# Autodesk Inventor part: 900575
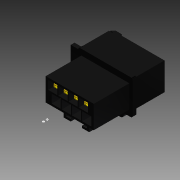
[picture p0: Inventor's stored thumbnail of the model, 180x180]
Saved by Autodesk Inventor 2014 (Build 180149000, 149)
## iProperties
Created: 2007-12
Part Number: 900575
Document SubType Name: Modeling
Designer: GS
Density: 1.06 g/cm^3
Categories: <MemberInstance><Categories><Category DisplayName="" Mnemonic="CABLEANDHARNESS" InternalName="e4a7e005-5e42-4d16-b293-125e7f0d0512"><Category DisplayName="" Mne
Mass: 9.17765 g
Surface Area: 145.988 cm^2
Volume: 8.65816 cm^3
Material: ABS Plastic
Description: R9 MOTOR CONNECTOR
Appearance: Glossy - Black
GlobalPropertyList: <PropertyList/>
Component Category: Electrical
Author: GS
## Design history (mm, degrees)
sketch "Sketch1"
  geometry: L1 (-12.001, 7.201)-(12.636, 7.201); L2 (12.636, 7.201)-(12.636, -7.201); L3 (12.636, -7.201)-(-12.001, -7.201); L4 (-12.636, -6.566)-(-12.636, 6.134); L5 (-12.636, 6.134)-(-16.447, 6.134); L6 (-16.447, 6.134)-(-16.447, -6.566); L7 (-16.447, -6.566)-(-12.636, -6.566); L8 (-12.636, -6.566)-(-12.636, 6.134); L9 (-7.81, -7.201)-(-6.54, -7.201); L10 (-6.54, -7.201)-(-6.54, -9.614); L11 (-6.54, -9.614)-(-7.81, -9.614); L12 (-7.81, -9.614)-(-7.81, -7.201); L13 (6.668, -7.201)-(7.938, -7.201); L14 (7.938, -7.201)-(7.938, -9.614); L15 (7.938, -9.614)-(6.668, -9.614); L16 (6.668, -9.614)-(6.668, -7.201); L17 (-12.636, -6.566)-(-12.001, -6.566); L18 (-12.001, -6.566)-(-12.001, -7.201); L19 (-12.636, 6.134)-(-12.002, 6.134); L20 (-12.002, 6.134)-(-12.001, 7.201); L21 (0, 7.201)-(0, 0); 1 further point
  constraints: 42 end point, 9 parallel, 8 perpendicular, 4 horizontal, 3 collinear, 2 point on line, 1 horizontal alignment, 1 midpoint, 1 vertical alignment, 1 other
  dimensions: "d1" = 14.4018 distance of L1.end L2.end; "d2" = 12.7 distance of L5.end L6.end; "d3" = 1.0668 distance between parallel lines of L1 L5; "d4" = 3.81 distance of L4.end L5.end; "d5" = 1.27 distance between parallel lines of L10 L12; "d7" = 13.208 distance between parallel lines of L10 L16; "d8" = 2.413 distance between parallel lines of L3 L11; "d11" = 4.826 distance between parallel lines of L4 L12; "d12" = 25.273 distance between parallel lines of L2 L4; "d13" = 0.635 distance between parallel lines of L4 L18
extrude "Extrusion1" new body sketch "Sketch1" distance "d9" = 16.3068; taper "d10" = 0 deg
sketch "Sketch4"
  geometry: L1 (-14.199, 9.017)-(14.199, 9.017); L2 (14.199, 9.017)-(14.199, -9.017); L3 (14.199, -9.017)-(-14.199, -9.017); L4 (-14.199, -9.017)-(-14.199, 9.017); L5 (-14.199, 8.026)-(-18.136, 8.026); L6 (-18.136, 8.026)-(-18.136, -8.23); L7 (-18.136, -8.23)-(-14.199, -8.23); L8 (-14.199, -8.23)-(-14.199, 8.026); L9 (-9.601, -9.017)-(-4.978, -9.017); L10 (-4.978, -9.017)-(-4.978, -11.608); L11 (-4.978, -11.608)-(-9.601, -11.608); L12 (-9.601, -11.608)-(-9.601, -9.017); L13 (4.978, -9.017)-(9.601, -9.017); L14 (9.601, -9.017)-(9.601, -11.608); L15 (9.601, -11.608)-(4.978, -11.608); L16 (4.978, -11.608)-(4.978, -9.017); 3 further points
  constraints: 32 end point, 8 parallel, 4 horizontal, 4 perpendicular, 3 point on line, 2 collinear, 2 midpoint, 1 horizontal alignment, 1 vertical alignment
  dimensions: "d23" = 18.034 distance from line of L3 point (0, 9.017); "d24" = 28.3972 distance between parallel lines of L2 L4; "d25" = 16.256 distance of L5.end L6.end; "d26" = 3.937 distance of L5.start L5.end; "d27" = 0.9906 distance between parallel lines of L1 L5; "d45" = 2.5908 distance between parallel lines of L9 L11; "d46" = 4.5974 distance between parallel lines of L8 L12; "d47" = 9.9568 distance between parallel lines of L16 L10; "d48" = 4.6228 distance of L10.end L11.end
extrude "Extrusion2" join sketch "Sketch4" distance "d28" = 2; taper "d29" = 0 deg
sketch "Sketch3"
  geometry: L1 (12.573, 5.969)-(-12.573, 5.969); L2 (-12.573, 5.969)-(-12.573, -5.969); L3 (-12.573, -5.969)-(12.573, -5.969); L4 (12.573, -5.969)-(12.573, 5.969); L5 (14.199, 9.017)-(14.199, -9.017) reference; L6 (-14.199, 9.017)-(14.199, 9.017) reference; 1 further point
  constraints: 8 end point
  dimensions: "d30" = 25.146 distance between parallel lines of L4 L2; "d31" = 11.938 distance between parallel lines of L3 L1; "d32" = 14.1986 distance from line of L5 point (0, 0); "d33" = 9.017 distance from line of L6 point (0, 0); "d34" = 3.048 distance between parallel lines of L6 L1; "d35" = 1.6256 distance between parallel lines of L5 L4
extrude "Extrusion3" join sketch "Sketch3" distance "d36" = 18.669; taper "d37" = 0 deg
sketch "Sketch2"
  geometry: L1 (-9.525, -0.379)-(-9.525, -4.951); L2 (-9.525, -4.951)-(-4.699, -4.951); L3 (-4.699, -4.951)-(-4.699, -0.379); L4 (-4.699, -0.379)-(-9.525, -0.379); L5 (-11.303, 4.953)-(-11.303, 0.381); L6 (-11.303, 0.381)-(-6.477, 0.381); L7 (-6.477, 0.381)-(-6.477, 4.953); L8 (-6.477, 4.953)-(-11.303, 4.953); L9 (-12.573, 5.969)-(12.573, 5.969) reference; L10 (-12.573, -5.969)-(-12.573, 5.969) reference; L11 (12.573, -5.969)-(-12.573, -5.969) reference; L12 (12.573, 5.969)-(12.573, -5.969) reference
  constraints: 16 end point, 4 parallel
  dimensions: "d14" = 4.826 distance of L7.end L5.start; "d15" = 4.572 distance of L5.start L5.end; "d17" = 4.826 distance of L3.end L1.start (= d14); "d18" = 4.572 distance of L1.start L1.end (= d15); "d21" = 0.76 distance between parallel lines of L6 L4; "d22" = 1.778 distance between parallel lines of L5 L1; "d38" = 1.016 distance between parallel lines of L9 L8; "d39" = 1.27 distance between parallel lines of L10 L5
extrude "Extrusion4" cut sketch "Sketch2" stored distance "d40" = 18.669; taper "d41" = 0 deg
pattern_linear "Rectangular Pattern1" dims "d44" = 5.334
fillet "Fillet1" dims "d49" = 1.778
sketch "Sketch5"
  geometry: L1 (12.573, -5.969)-(-12.573, -5.969) reference; L2 (-6.756, -11.608)-(-7.823, -11.608) reference; L3 (-6.756, -11.608)-(-6.756, -5.969); L4 (-6.756, -11.608)-(-2.896, -11.608); L5 (-2.896, -11.608)-(-2.896, -10.338); L6 (-2.896, -10.338)-(-5.486, -10.338); L7 (-5.486, -10.338)-(-5.486, -5.969); L8 (-2.896, -10.338)-(-2.896, -5.969); L9 (7.823, -11.608)-(6.756, -11.608) reference; L10 (6.756, -11.608)-(6.756, -5.969); L11 (6.756, -11.608)-(2.896, -11.608); L12 (2.896, -11.608)-(2.896, -5.969); L13 (2.896, -10.338)-(5.486, -10.338); L14 (5.486, -10.338)-(5.486, -5.969); 1 further point
  constraints: 22 end point, 10 perpendicular, 7 point on line, 1 collinear, 1 parallel
  dimensions: "d50" = 1.27 distance between parallel lines of L3 L7; "d51" = 1.27 distance between parallel lines of L10 L14 (= d50); "d52" = 1.27 distance between parallel lines of L11 L13 (= d51); "d53" = 3.8608 distance between parallel lines of L8 L3; "d54" = 3.8608 distance between parallel lines of L10 L12 (= d53)
extrude "Extrusion5" join sketch "Sketch5" distance "d55" = 15.24; taper "d56" = 0 deg
extrude "Extrusion6" cut sketch "Sketch5" stored distance "d57" = 15.24; taper "d58" = 0 deg
sketch "Sketch6"
  geometry: L1 (13.017, 4.737)-(16.192, 4.737); L2 (16.192, 4.737)-(16.192, -4.915); L3 (16.192, -4.915)-(13.017, -4.915); L4 (13.017, -4.915)-(13.017, 4.737); L5 (12.002, 6.134)-(16.447, 6.134) reference; L6 (16.447, 6.134)-(16.447, -6.566) reference; 1 further point
  constraints: 8 end point, 2 parallel, 1 horizontal, 1 perpendicular
  dimensions: "d59" = 1.397 distance between parallel lines of L5 L1; "d60" = 3.175 distance of L1.start L1.end; "d61" = 0.254 distance between parallel lines of L6 L2; "d62" = 9.652 distance between parallel lines of L1 L3
extrude "Extrusion7" join sketch "Sketch6" distance "d63" = 3.175; taper "d64" = 0 deg
sketch "Sketch7"
  geometry: L1 (-3.175, 9.652)-(-3.175, 0) reference; L2 (0, 9.652)-(-3.175, 9.652) reference; L3 (-3.175, 9.652)-(-1.676, 9.652); L4 (-1.676, 9.652)-(-1.676, 0); L5 (-1.676, 0)-(-3.175, 0); L6 (-3.175, 0)-(-3.175, 9.652); 2 further points
  constraints: 8 end point, 2 parallel, 1 horizontal, 1 horizontal alignment, 1 midpoint, 1 perpendicular
  dimensions: "d65" = 1.4986 distance between parallel lines of L1 L4
extrude "Extrusion8" join sketch "Sketch7" distance "d66" = 1.27; taper "d67" = 0 deg
chamfer "Chamfer1" distance "d68" = 1.27; stored, may be unused: second distance "d69" = 3.175, angle "d70" = 48 deg
sketch "Sketch9"
  geometry: L1 (7.264, 4.318)-(10.516, 4.318); L2 (10.516, 4.318)-(10.516, 3.683); L3 (10.516, 3.683)-(7.264, 3.683); L4 (7.264, 3.683)-(7.264, 4.318); L5 (7.264, 2.616)-(10.516, 2.616); L6 (10.516, 2.616)-(10.516, 1.981); L7 (10.516, 1.981)-(7.264, 1.981); L8 (7.264, 1.981)-(7.264, 2.616); L9 (5.486, -1.979)-(8.738, -1.979); L10 (8.738, -1.979)-(8.738, -2.614); L11 (8.738, -2.614)-(5.486, -2.614); L12 (5.486, -2.614)-(5.486, -1.979); L13 (5.486, -3.681)-(8.738, -3.681); L14 (8.738, -3.681)-(8.738, -4.316); L15 (8.738, -4.316)-(5.486, -4.316); L16 (5.486, -4.316)-(5.486, -3.681); L17 (6.477, 4.953)-(11.303, 4.953) reference; L18 (11.303, 0.381)-(6.477, 0.381) reference; L19 (4.699, -0.379)-(9.525, -0.379) reference; L20 (9.525, -4.951)-(4.699, -4.951) reference; L21 (4.699, -4.951)-(4.699, -0.379) reference; L22 (9.525, -0.379)-(9.525, -4.951) reference; L23 (11.303, 4.953)-(11.303, 0.381) reference; L24 (6.477, 0.381)-(6.477, 4.953) reference; 5 further points
  constraints: 32 end point, 8 parallel, 6 equal length, 4 horizontal, 4 midpoint, 4 perpendicular, 2 collinear, 2 vertical alignment
  dimensions: "d71" = 3.2512 distance of L1.start L1.end; "d72" = 1.27 distance between parallel lines of L17 L3; "d74" = 0.635 distance of L1.end L2.end; "d75" = 2.2352 distance between parallel lines of L18 L5; "d76" = 2.2352 distance between parallel lines of L19 L11 (= d75); "d77" = 1.27 distance between parallel lines of L20 L13 (= d72)
extrude "Extrusion9" join sketch "Sketch9" distance "d78" = 12.7; taper "d79" = 0 deg
sketch "Sketch12"
  geometry: L1 (0, 0.635)-(12.7, 0.635) reference; L2 (0, 0)-(12.7, 0) reference; L3 (0, -1.067)-(12.7, -1.067) reference; L4 (0, -1.702)-(12.7, -1.702) reference; L5 (23.101, -1.165)-(34.926, -1.165); L6 (23.101, -1.8)-(34.926, -1.8); L7 (34.926, -1.8)-(34.926, -1.165); L8 (34.926, -1.927)-(34.926, -2.562); L9 (34.926, -1.927)-(23.101, -1.927); L10 (34.926, -2.562)-(23.101, -2.562); L11 (12.7, 0.635)-(12.7, 0); L12 (12.7, -1.067)-(12.7, -1.702); A1 r 17.012 centre (12.7, -16.377) between (18.416, -0.354) and (12.7, 0.635); A2 r 13.945 centre (23.101, 12.781) between (18.416, -0.354) and (23.101, -1.165); A3 r 16.377 centre (12.7, -16.377) between (18.202, -0.952) and (12.7, 0); A4 r 14.58 centre (23.101, 12.781) between (18.202, -0.952) and (23.101, -1.8); A5 r 28.533 centre (23.101, 26.606) between (18.416, -1.539) and (23.101, -1.927); A6 r 34.807 centre (12.7, -35.874) between (18.416, -1.539) and (12.7, -1.067); A7 r 28.533 centre (23.101, 25.971) between (18.416, -2.174) and (23.101, -2.562); A8 r 34.807 centre (12.7, -36.509) between (18.416, -2.174) and (12.7, -1.702); 1 further point
  constraints: 17 point on circle, 16 end point, 9 tangent, 8 centre point, 4 parallel, 3 collinear, 2 vertical alignment, 1 perpendicular, 1 other
  dimensions: "d85" = 0.635 distance of L6.end L5.end; "d86" = 17.01202 radius of A1; "d87" = 13.94546 radius of A2; "d88" = 11.8245 distance of L5.start L5.end; "d89" = 16.51 horizontal distance of L5.end A1.start; "d90" = 0.635 distance of L8.start L8.end (= d85); "d91" = 0.127 distance between parallel lines of L6 L9; "d92" = 0.635 distance of A8.centre A6.centre (= d85); "d93" = 16.51 distance from line of L8 A5.start (= d89)
extrude "Extrusion10" join sketch "Sketch12" stored distance "d94" = 12.7; taper "d95" = 0 deg
sketch "Sketch13"
  geometry: L1 (0, 0.635)-(12.7, 0.635) reference; L2 (0, 0)-(12.7, 0) reference; L3 (0, -1.067)-(12.7, -1.067) reference; L4 (0, -1.702)-(12.7, -1.702) reference; L5 (34.926, 5.133)-(23.101, 5.133) reference; L6 (23.101, 1.581)-(34.926, 1.581); L7 (34.926, 1.581)-(34.926, 0.946); L8 (34.926, 0.946)-(23.101, 0.946); L9 (34.926, 0.819)-(23.101, 0.819); L10 (23.101, 0.819)-(34.926, 0.819); L11 (34.926, 0.184)-(34.926, 0.819); L12 (34.926, 0.184)-(23.101, 0.184); L13 (12.7, 0.635)-(12.7, 0); L14 (12.7, -1.067)-(12.7, -1.702); A1 r 22.86 centre (12.7, 21.158) between (12.7, -1.702) and (20.724, -0.247); A2 r 6.774 centre (23.101, -6.59) between (23.101, 0.184) and (20.724, -0.247); A3 r 22.552 centre (12.7, 21.485) between (12.7, -1.067) and (20.616, 0.368); A4 r 7.082 centre (23.101, -6.264) between (23.101, 0.819) and (20.616, 0.368); A5 r 31.696 centre (12.7, 32.331) between (12.7, 0.635) and (18.416, 1.155); A6 r 31.696 centre (12.7, 31.696) between (12.7, 0) and (18.416, 0.52); A7 r 25.983 centre (23.101, -24.402) between (23.101, 1.581) and (18.416, 1.155); A8 r 25.983 centre (23.101, -25.037) between (23.101, 0.946) and (18.416, 0.52); A9 r 17.012 centre (12.7, -10.08) between (18.416, 5.943) and (12.7, 6.932) reference; A10 r 13.945 centre (23.101, 19.078) between (18.416, 5.943) and (23.101, 5.133) reference; A11 r 34.807 centre (12.7, -29.576) between (18.416, 4.758) and (12.7, 5.23) reference; A12 r 28.533 centre (23.101, 32.903) between (18.416, 4.758) and (23.101, 4.371) reference; A13 r 16.377 centre (12.7, -10.08) between (18.202, 5.345) and (12.7, 6.297) reference; A14 r 14.58 centre (23.101, 19.078) between (18.202, 5.345) and (23.101, 4.498) reference; A15 r 34.807 centre (12.7, -30.211) between (18.416, 4.123) and (12.7, 4.595) reference; A16 r 28.533 centre (23.101, 32.268) between (18.416, 4.123) and (23.101, 3.736) reference; 3 further points
  constraints: 19 end point, 18 point on circle, 12 tangent, 11 vertical alignment, 8 centre point, 5 perpendicular, 3 collinear, 3 parallel, 2 equal length
  dimensions: "d96" = 0.635 distance of L6.end L7.end; "d97" = 0.127 distance between parallel lines of L8 L9; "d98" = 22.86 radius of A1
extrude "Extrusion11" join sketch "Sketch13" stored distance "d99" = 12.7; taper "d100" = 0 deg
pattern_linear "Rectangular Pattern2" dims "d103" = 5.334
sketch "Pin_1,4_Positioning"
  geometry: L1 (0, 0)-(3.251, 0) reference; L2 (0, -0.127)-(3.251, -0.127) reference; L3 (1.626, 0)-(1.626, -0.127); L4 (1.778, -3.552)-(5.029, -3.552) reference; L5 (1.778, -3.679)-(5.029, -3.679) reference; L6 (3.404, -3.552)-(3.404, -3.679); 3 further points
  constraints: 6 midpoint, 4 end point
node "1"
node "2"
node "3"
node "4"
node "5"
node "6"
node "7"
node "8"
fillet "Fillet2" dims "d104" = 0.2032
fillet "Fillet3" dims "d105" = 1
workpoint "Work Point9"
workpoint "Work Point10"
body "Solid1"
node "Projected Loop1"
other parameters: "d106" = 0, "d107" = 0, "d108" = 0
